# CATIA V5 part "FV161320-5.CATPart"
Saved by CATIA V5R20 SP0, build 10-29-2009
Part number: FV161320-5
Revision: ANY
Definition: UNKNOWN
Nomenclature: FV161320-5
Source: Unknown
Bounding box of the stored display mesh (mm): x -5.476 to 5.476, y 0 to 6.05, z -5 to 5
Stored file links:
  C:\Users\Utente\Desktop\IO LAVORO\3D X SITO CF\CUMSA\3D files FV\FV 161320\FV161320-5.CATPart
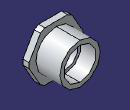
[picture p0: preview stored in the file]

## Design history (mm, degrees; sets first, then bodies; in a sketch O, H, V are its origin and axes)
Body1 "Cortar-Extruir2" (main body)
  Solid1: solid without history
